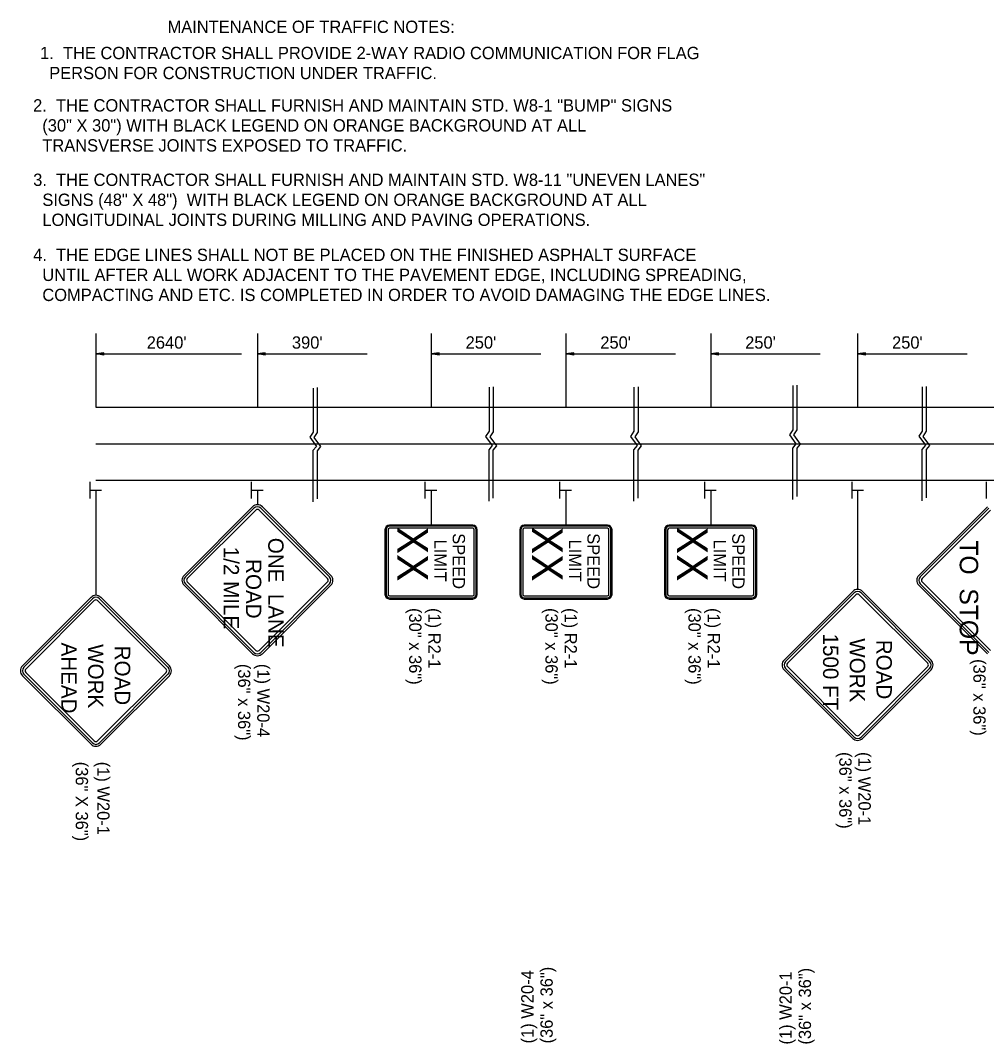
# Model space of a CAD drawing. Extents: x 1927831 to 1930787, y 596452 to 597699.
# Drawn here: x 1927871.5 to 1928342.4, y 597195.5 to 597694.1 of the extents above; entities that cross this region are included whole.
import ezdxf

# ---------------------------------------------------------------- set-up
doc = ezdxf.new("R2010")
doc.units = 0
for name, color, linetype in [('Default', 7, 'Continuous'), ('P_TC_Signs_Permanent', 7, 'Continuous'), ('P_TC_Signs_Temporary', 7, 'Continuous'), ('R_Border', 7, 'Continuous')]:
    doc.layers.add(name, color=color, linetype=linetype)

msp = doc.modelspace()

# ---------------------------------------------------------------- linework, layer by layer
at = {"layer": 'Default'}
for p, q in [((1927908.3, 597541.61), (1927908.3, 597505.58)), ((1927987.03, 597541.61), (1927987.03, 597505.56)), ((1928071.69, 597541.61), (1928071.69, 597505.58)), ((1928137.35, 597541.61), (1928137.35, 597505.58)), ((1928207.95, 597541.61), (1928207.95, 597505.58)), ((1928279.55, 597541.61), (1928279.55, 597505.58)), ((1927912.18, 597532.14), (1927908.34, 597531.57)), ((1927912.18, 597530.99), (1927908.34, 597531.57)), ((1927908.34, 597531.57), (1927979.22, 597531.57)), ((1927912.18, 597532.05), (1927908.98, 597531.57)), ((1927912.18, 597531.09), (1927908.98, 597531.57)), ((1927912.18, 597531.95), (1927909.64, 597531.57)), ((1927912.18, 597531.18), (1927909.64, 597531.57)), ((1927912.18, 597531.85), (1927910.28, 597531.57)), ((1927912.18, 597531.28), (1927910.28, 597531.57)), ((1927912.18, 597531.75), (1927910.93, 597531.57)), ((1927912.18, 597531.38), (1927910.93, 597531.57)), ((1927912.18, 597531.66), (1927911.57, 597531.57)), ((1927912.18, 597531.48), (1927911.57, 597531.57)), ((1927912.18, 597530.99), (1927912.18, 597532.14)), ((1927990.87, 597532.14), (1927987.03, 597531.57)), ((1927990.87, 597530.99), (1927987.03, 597531.57)), ((1927987.03, 597531.57), (1928040.44, 597531.57)), ((1927990.87, 597532.05), (1927987.67, 597531.57)), ((1927990.87, 597531.09), (1927987.67, 597531.57)), ((1927990.87, 597531.95), (1927988.33, 597531.57)), ((1927990.87, 597531.18), (1927988.33, 597531.57)), ((1927990.87, 597531.85), (1927988.97, 597531.57)), ((1927990.87, 597531.28), (1927988.97, 597531.57)), ((1927990.87, 597531.75), (1927989.62, 597531.57)), ((1927990.87, 597531.38), (1927989.62, 597531.57)), ((1927990.87, 597531.66), (1927990.26, 597531.57)), ((1927990.87, 597531.48), (1927990.26, 597531.57)), ((1927990.87, 597530.99), (1927990.87, 597532.14)), ((1928075.53, 597532.14), (1928071.69, 597531.57)), ((1928071.69, 597531.57), (1928125.09, 597531.57)), ((1928075.53, 597530.99), (1928071.69, 597531.57)), ((1928075.53, 597532.05), (1928072.33, 597531.57)), ((1928075.53, 597531.09), (1928072.33, 597531.57)), ((1928075.53, 597531.95), (1928072.99, 597531.57)), ((1928075.53, 597531.18), (1928072.99, 597531.57)), ((1928075.53, 597531.85), (1928073.63, 597531.57)), ((1928075.53, 597531.28), (1928073.63, 597531.57)), ((1928075.53, 597531.75), (1928074.28, 597531.57)), ((1928075.53, 597531.38), (1928074.28, 597531.57)), ((1928075.53, 597531.66), (1928074.92, 597531.57)), ((1928075.53, 597531.48), (1928074.92, 597531.57)), ((1928075.53, 597530.99), (1928075.53, 597532.14)), ((1928141.18, 597532.14), (1928137.35, 597531.57)), ((1928137.35, 597531.57), (1928190.75, 597531.57)), ((1928141.18, 597530.99), (1928137.35, 597531.57)), ((1928141.18, 597532.05), (1928137.99, 597531.57)), ((1928141.18, 597531.09), (1928137.99, 597531.57)), ((1928141.18, 597531.95), (1928138.65, 597531.57)), ((1928141.18, 597531.18), (1928138.65, 597531.57)), ((1928141.18, 597531.85), (1928139.29, 597531.57)), ((1928141.18, 597531.28), (1928139.29, 597531.57)), ((1928141.18, 597531.75), (1928139.94, 597531.57)), ((1928141.18, 597531.38), (1928139.94, 597531.57)), ((1928141.18, 597531.66), (1928140.58, 597531.57)), ((1928141.18, 597531.48), (1928140.58, 597531.57)), ((1928141.18, 597530.99), (1928141.18, 597532.14)), ((1928211.79, 597532.14), (1928207.95, 597531.57)), ((1928207.95, 597531.57), (1928261.36, 597531.59)), ((1928211.79, 597530.99), (1928207.95, 597531.57)), ((1928211.79, 597532.05), (1928208.6, 597531.57)), ((1928211.79, 597531.09), (1928208.6, 597531.57)), ((1928211.79, 597531.95), (1928209.26, 597531.57)), ((1928211.79, 597531.18), (1928209.26, 597531.57)), ((1928211.79, 597531.85), (1928209.89, 597531.57)), ((1928211.79, 597531.28), (1928209.89, 597531.57)), ((1928211.79, 597531.75), (1928210.55, 597531.57)), ((1928211.79, 597531.38), (1928210.55, 597531.57)), ((1928211.79, 597531.66), (1928211.19, 597531.57)), ((1928211.79, 597531.48), (1928211.19, 597531.57)), ((1928211.79, 597530.99), (1928211.79, 597532.14)), ((1928283.39, 597532.16), (1928279.55, 597531.59)), ((1928279.55, 597531.59), (1928332.95, 597531.59)), ((1928283.39, 597531.01), (1928279.55, 597531.59)), ((1928283.39, 597532.07), (1928280.19, 597531.59)), ((1928283.39, 597531.11), (1928280.19, 597531.59)), ((1928283.39, 597531.97), (1928280.85, 597531.59)), ((1928283.39, 597531.2), (1928280.85, 597531.59)), ((1928283.39, 597531.87), (1928281.49, 597531.59)), ((1928283.39, 597531.3), (1928281.49, 597531.59)), ((1928283.39, 597531.77), (1928282.14, 597531.59)), ((1928283.39, 597531.4), (1928282.14, 597531.59)), ((1928283.39, 597531.68), (1928282.78, 597531.59)), ((1928283.39, 597531.5), (1928282.78, 597531.59)), ((1928283.39, 597531.01), (1928283.39, 597532.16)), ((1927908.3, 597505.58), (1928044.85, 597505.58)), ((1928044.85, 597505.58), (1929173.7, 597505.58)), ((1927908.3, 597487.79), (1929173.7, 597487.79)), ((1927905.45, 597461.2), (1927905.45, 597469.2)), ((1927908.3, 597470), (1928044.85, 597470)), ((1927984.18, 597461.2), (1927984.18, 597469.2)), ((1928044.85, 597470), (1929173.7, 597470)), ((1928068.84, 597461.2), (1928068.84, 597469.2)), ((1928134.5, 597461.2), (1928134.5, 597469.2)), ((1928205.1, 597461.2), (1928205.1, 597469.2)), ((1928276.87, 597461.2), (1928276.87, 597469.2)), ((1928342.35, 597461.2), (1928342.35, 597469.2)), ((1927905.57, 597465.18), (1927911.03, 597465.18)), ((1927984.3, 597465.18), (1927989.77, 597465.18)), ((1928068.96, 597465.18), (1928074.42, 597465.18)), ((1928134.61, 597465.18), (1928140.08, 597465.18)), ((1928205.22, 597465.18), (1928210.69, 597465.18)), ((1928276.99, 597465.18), (1928282.45, 597465.18))]:
    msp.add_line(p, q, dxfattribs=at)
for points in [[(1928014.17, 597514.95), (1928014.17, 597493.43), (1928012.5, 597490.96), (1928015.74, 597486.53), (1928014.04, 597484.48), (1928014.03, 597459.46)], [(1928016.21, 597515.15), (1928016.21, 597493.34), (1928014.55, 597490.87), (1928017.79, 597486.44), (1928016.08, 597484.4), (1928016.08, 597460.9)], [(1928099.91, 597515.4), (1928099.91, 597493.87), (1928098.25, 597491.4), (1928101.48, 597486.97), (1928099.78, 597484.93), (1928099.77, 597459.9)], [(1928101.95, 597515.49), (1928101.95, 597493.69), (1928100.29, 597491.21), (1928103.53, 597486.78), (1928101.82, 597484.74), (1928101.82, 597461.24)], [(1928170.52, 597515.4), (1928170.52, 597493.87), (1928168.85, 597491.4), (1928172.09, 597486.97), (1928170.39, 597484.93), (1928170.38, 597459.9)], [(1928172.56, 597515.49), (1928172.56, 597493.69), (1928170.9, 597491.21), (1928174.14, 597486.78), (1928172.43, 597484.74), (1928172.43, 597461.24)], [(1928247.96, 597516.18), (1928247.96, 597494.66), (1928246.3, 597492.19), (1928249.53, 597487.76), (1928247.83, 597485.71), (1928247.82, 597460.68)], [(1928250, 597516.37), (1928250, 597494.57), (1928248.34, 597492.1), (1928251.58, 597487.67), (1928249.87, 597485.62), (1928249.87, 597462.12)], [(1928311, 597515.51), (1928311, 597493.99), (1928309.34, 597491.51), (1928312.58, 597487.08), (1928310.87, 597485.04), (1928310.87, 597460.01)], [(1928313.04, 597515.7), (1928313.04, 597493.9), (1928311.38, 597491.43), (1928314.62, 597487), (1928312.91, 597484.95), (1928312.91, 597461.45)]]:
    msp.add_lwpolyline(points, dxfattribs=at)
at = {"layer": 'P_TC_Signs_Permanent'}
for p, q in [((1928342.81, 597457.08), (1928309.4, 597423.67)), ((1928343.48, 597456.42), (1928310.07, 597423.01)), ((1928344.41, 597455.49), (1928310.99, 597422.08)), ((1928049.19, 597445.9), (1928049.19, 597414.4)), ((1928049.75, 597445.9), (1928049.75, 597414.4)), ((1928050.69, 597445.9), (1928050.69, 597414.4)), ((1928091.94, 597448.15), (1928051.44, 597448.15)), ((1928091.94, 597447.59), (1928051.44, 597447.59)), ((1928091.94, 597446.65), (1928051.44, 597446.65)), ((1928092.69, 597414.4), (1928092.69, 597445.9)), ((1928093.63, 597414.4), (1928093.63, 597445.9)), ((1928094.19, 597414.4), (1928094.19, 597445.9)), ((1928114.85, 597445.9), (1928114.85, 597414.4)), ((1928115.41, 597445.9), (1928115.41, 597414.4)), ((1928116.35, 597445.9), (1928116.35, 597414.4)), ((1928157.6, 597448.15), (1928117.1, 597448.15)), ((1928157.6, 597447.59), (1928117.1, 597447.59)), ((1928157.6, 597446.65), (1928117.1, 597446.65)), ((1928158.35, 597414.4), (1928158.35, 597445.9)), ((1928159.28, 597414.4), (1928159.28, 597445.9)), ((1928159.85, 597414.4), (1928159.85, 597445.9)), ((1928185.45, 597445.9), (1928185.45, 597414.4)), ((1928186.02, 597445.9), (1928186.02, 597414.4)), ((1928186.95, 597445.9), (1928186.95, 597414.4)), ((1928228.2, 597448.15), (1928187.7, 597448.15)), ((1928228.2, 597447.59), (1928187.7, 597447.59)), ((1928228.2, 597446.65), (1928187.7, 597446.65)), ((1928228.95, 597414.4), (1928228.95, 597445.9)), ((1928229.89, 597414.4), (1928229.89, 597445.9)), ((1928230.45, 597414.4), (1928230.45, 597445.9)), ((1928310.07, 597419.56), (1928343.48, 597386.15)), ((1928310.99, 597420.49), (1928344.41, 597387.08)), ((1928309.4, 597418.89), (1928342.81, 597385.48)), ((1928051.44, 597413.65), (1928091.94, 597413.65)), ((1928051.44, 597412.71), (1928091.94, 597412.71)), ((1928051.44, 597412.15), (1928091.94, 597412.15)), ((1928117.1, 597413.65), (1928157.6, 597413.65)), ((1928117.1, 597412.71), (1928157.6, 597412.71)), ((1928117.1, 597412.15), (1928157.6, 597412.15)), ((1928187.7, 597413.65), (1928228.2, 597413.65)), ((1928187.7, 597412.71), (1928228.2, 597412.71)), ((1928187.7, 597412.15), (1928228.2, 597412.15))]:
    msp.add_line(p, q, dxfattribs=at)
for centre, radius, start, end in [((1928051.44, 597445.9), 2.25, 90, 180), ((1928051.44, 597445.9), 1.69, 90, 180), ((1928051.44, 597445.9), 0.75, 90, 180), ((1928091.94, 597445.9), 2.25, 360, 90), ((1928091.94, 597445.9), 1.69, 360, 90), ((1928091.94, 597445.9), 0.75, 360, 90), ((1928117.1, 597445.9), 2.25, 90, 180), ((1928117.1, 597445.9), 1.69, 90, 180), ((1928117.1, 597445.9), 0.75, 90, 180), ((1928157.6, 597445.9), 2.25, 360, 90), ((1928157.6, 597445.9), 1.69, 360, 90), ((1928157.6, 597445.9), 0.75, 360, 90), ((1928187.7, 597445.9), 2.25, 90, 180), ((1928187.7, 597445.9), 1.69, 90, 180), ((1928187.7, 597445.9), 0.75, 90, 180), ((1928228.2, 597445.9), 2.25, 360, 90), ((1928228.2, 597445.9), 1.69, 360, 90), ((1928228.2, 597445.9), 0.75, 360, 90), ((1928311.79, 597421.28), 3.37, 135, 225), ((1928311.79, 597421.28), 2.44, 135, 225), ((1928311.79, 597421.28), 1.13, 135, 225), ((1928051.44, 597414.4), 2.25, 180, 270), ((1928051.44, 597414.4), 1.69, 180, 270), ((1928051.44, 597414.4), 0.75, 180, 270), ((1928091.94, 597414.4), 2.25, 270, 360), ((1928091.94, 597414.4), 1.69, 270, 360), ((1928091.94, 597414.4), 0.75, 270, 360), ((1928117.1, 597414.4), 2.25, 180, 270), ((1928117.1, 597414.4), 1.69, 180, 270), ((1928117.1, 597414.4), 0.75, 180, 270), ((1928157.6, 597414.4), 2.25, 270, 360), ((1928157.6, 597414.4), 1.69, 270, 360), ((1928157.6, 597414.4), 0.75, 270, 360), ((1928187.7, 597414.4), 2.25, 180, 270), ((1928187.7, 597414.4), 1.69, 180, 270), ((1928187.7, 597414.4), 0.75, 180, 270), ((1928228.2, 597414.4), 2.25, 270, 360), ((1928228.2, 597414.4), 1.69, 270, 360), ((1928228.2, 597414.4), 0.75, 270, 360)]:
    msp.add_arc(centre, radius, start, end, dxfattribs=at)
at = {"layer": 'P_TC_Signs_Temporary'}
for p, q in [((1927951.24, 597423.67), (1927984.65, 597457.08)), ((1927951.9, 597423), (1927985.31, 597456.42)), ((1927952.83, 597422.08), (1927986.24, 597455.49)), ((1927987.83, 597455.49), (1928021.24, 597422.08)), ((1927988.76, 597456.42), (1928022.17, 597423)), ((1927989.42, 597457.08), (1928022.83, 597423.67)), ((1927985.31, 597386.15), (1927951.9, 597419.56)), ((1927986.24, 597387.07), (1927952.83, 597420.49)), ((1928021.24, 597420.49), (1927987.83, 597387.07)), ((1928022.17, 597419.56), (1927988.76, 597386.15)), ((1927984.65, 597385.48), (1927951.24, 597418.89)), ((1928022.83, 597418.89), (1927989.42, 597385.48)), ((1928243.75, 597382.42), (1928277.16, 597415.83)), ((1928244.41, 597381.76), (1928277.82, 597415.17)), ((1928281.27, 597415.17), (1928314.68, 597381.76)), ((1928281.93, 597415.83), (1928315.35, 597382.42)), ((1927872.5, 597379.57), (1927905.91, 597412.98)), ((1927873.17, 597378.91), (1927906.58, 597412.32)), ((1927874.09, 597377.98), (1927907.5, 597411.39)), ((1927909.1, 597411.39), (1927942.51, 597377.98)), ((1927910.02, 597412.32), (1927943.43, 597378.91)), ((1927910.69, 597412.98), (1927944.1, 597379.57)), ((1928245.34, 597380.83), (1928278.75, 597414.24)), ((1928280.34, 597414.24), (1928313.75, 597380.83)), ((1927905.91, 597341.39), (1927872.5, 597374.8)), ((1927906.58, 597342.05), (1927873.17, 597375.46)), ((1927907.5, 597342.98), (1927874.09, 597376.39)), ((1927942.51, 597376.39), (1927909.1, 597342.98)), ((1927943.43, 597375.46), (1927910.02, 597342.05)), ((1927944.1, 597374.8), (1927910.69, 597341.39)), ((1928277.16, 597344.24), (1928243.75, 597377.65)), ((1928277.82, 597344.9), (1928244.41, 597378.31)), ((1928278.75, 597345.83), (1928245.34, 597379.24)), ((1928313.75, 597379.24), (1928280.34, 597345.83)), ((1928314.68, 597378.31), (1928281.27, 597344.9)), ((1928315.35, 597377.65), (1928281.93, 597344.24))]:
    msp.add_line(p, q, dxfattribs=at)
for centre, radius, start, end in [((1927987.03, 597454.69), 3.37, 45, 135), ((1927987.03, 597454.69), 2.44, 45, 135), ((1927987.03, 597454.69), 1.12, 45, 135), ((1927953.62, 597421.28), 3.37, 135, 225), ((1927953.62, 597421.28), 2.44, 135, 225), ((1927953.62, 597421.28), 1.13, 135, 225), ((1928020.44, 597421.28), 1.13, 315, 45), ((1928020.44, 597421.28), 2.44, 315, 45), ((1928020.44, 597421.28), 3.37, 315, 45), ((1928279.55, 597413.45), 3.37, 45, 135), ((1928279.55, 597413.45), 2.44, 45, 135), ((1928279.55, 597413.45), 1.12, 45, 135), ((1927908.3, 597410.59), 3.37, 45, 135), ((1927908.3, 597410.59), 2.44, 45, 135), ((1927908.3, 597410.59), 1.12, 45, 135), ((1927987.03, 597387.87), 3.37, 225, 315), ((1927987.03, 597387.87), 2.44, 225, 315), ((1927987.03, 597387.87), 1.12, 225, 315), ((1927874.89, 597377.18), 3.37, 135, 225), ((1927941.71, 597377.18), 3.37, 315, 45), ((1928246.14, 597380.04), 3.37, 135, 225), ((1928246.14, 597380.04), 2.44, 135, 225), ((1928246.14, 597380.04), 1.13, 135, 225), ((1928312.96, 597380.04), 1.13, 315, 45), ((1928312.96, 597380.04), 2.44, 315, 45), ((1928312.96, 597380.04), 3.37, 315, 45), ((1927874.89, 597377.18), 2.44, 135, 225), ((1927874.89, 597377.18), 1.13, 135, 225), ((1927941.71, 597377.18), 1.13, 315, 45), ((1927941.71, 597377.18), 2.44, 315, 45), ((1928279.55, 597346.63), 2.44, 225, 315), ((1928279.55, 597346.63), 1.12, 225, 315), ((1927908.3, 597343.77), 3.38, 225, 315), ((1927908.3, 597343.77), 2.44, 225, 315), ((1927908.3, 597343.77), 1.12, 225, 315), ((1928279.55, 597346.63), 3.37, 225, 315)]:
    msp.add_arc(centre, radius, start, end, dxfattribs=at)
at = {"layer": 'R_Border'}
for p, q in [((1927908.3, 597465.18), (1927908.3, 597413.97)), ((1927987.03, 597465.18), (1927987.03, 597458.07)), ((1928071.69, 597465.18), (1928071.69, 597448.15)), ((1928137.35, 597465.18), (1928137.35, 597448.15)), ((1928207.95, 597465.18), (1928207.95, 597448.15)), ((1928279.55, 597465.18), (1928279.55, 597416.82))]:
    msp.add_line(p, q, dxfattribs=at)

# ---------------------------------------------------------------- texts
at = {"layer": 'Default'}
for s, p in [("2640'", (1927933.06, 597534.16)), ("390'", (1928003.83, 597534.16)), ("250'", (1928088.49, 597534.18)), ("250'", (1928154.15, 597534.16)), ("250'", (1928224.76, 597534.16)), ("250'", (1928296.35, 597534.16))]:
    msp.add_text(s, height=6, rotation=360, dxfattribs=at).set_placement(p)
at = {"layer": 'P_TC_Signs_Permanent'}
for s, height, p in [('XX', 15, (1928055.19, 597447.45)), ('XX', 15, (1928120.85, 597447.45)), ('XX', 15, (1928191.45, 597447.45)), ('LIMIT', 6, (1928073.19, 597441.13)), ('SPEED', 6, (1928082.19, 597444.22)), ('LIMIT', 6, (1928138.85, 597441.13)), ('SPEED', 6, (1928147.85, 597444.22)), ('LIMIT', 6, (1928209.45, 597441.13)), ('SPEED', 6, (1928218.45, 597444.22))]:
    msp.add_text(s, height=height, rotation=270, dxfattribs=at).set_placement(p)
at = {"layer": 'P_TC_Signs_Temporary'}
for s, height, p in [('ONE  LANE', 7.5, (1927992.28, 597441.98)), ('TO  STOP', 9, (1928329.33, 597440.75)), ('1/2 MILE', 7.5, (1927970.53, 597437.6)), ('ROAD', 7.5, (1927981.41, 597431.59)), ('1500 FT', 7.5, (1928262.71, 597395.33)), (' AHEAD ', 7.5, (1927891.47, 597393.72)), ('WORK', 7.5, (1927904.49, 597390.17)), ('WORK', 7.5, (1928275.74, 597393.03)), (' ROAD ', 7.5, (1928288.76, 597395.06)), (' ROAD ', 7.5, (1927917.51, 597392.2))]:
    msp.add_text(s, height=height, rotation=270, dxfattribs=at).set_placement(p)
at = {"layer": 'R_Border'}
for s, height, rotation, p in [('MAINTENANCE OF TRAFFIC NOTES:', 6, 360, (1927943.21, 597688)), ('1.  THE CONTRACTOR SHALL PROVIDE 2-WAY RADIO COMMUNICATION FOR FLAG ', 6, 360, (1927881.08, 597675.24)), ('  PERSON FOR CONSTRUCTION UNDER TRAFFIC.', 6, 360, (1927881.08, 597665.49)), ('2.  THE CONTRACTOR SHALL FURNISH AND MAINTAIN STD. W8-1 "BUMP" SIGNS', 6, 360, (1927877.7, 597649.72)), ('  (30" X 30") WITH BLACK LEGEND ON ORANGE BACKGROUND AT ALL ', 6, 360, (1927877.7, 597639.97)), ('  TRANSVERSE JOINTS EXPOSED TO TRAFFIC.', 6, 360, (1927877.7, 597630.22)), ('3.  THE CONTRACTOR SHALL FURNISH AND MAINTAIN STD. W8-11 "UNEVEN LANES" ', 6, 360, (1927877.73, 597613.46)), ('  SIGNS (48" X 48")  WITH BLACK LEGEND ON ORANGE BACKGROUND AT ALL ', 6, 360, (1927877.73, 597603.71)), ('  LONGITUDINAL JOINTS DURING MILLING AND PAVING OPERATIONS.', 6, 360, (1927877.73, 597593.96)), ('4.  THE EDGE LINES SHALL NOT BE PLACED ON THE FINISHED ASPHALT SURFACE', 6, 360, (1927877.73, 597576.87)), ('  UNTIL AFTER ALL WORK ADJACENT TO THE PAVEMENT EDGE, INCLUDING SPREADING,', 6, 360, (1927877.73, 597567.12)), ('  COMPACTING AND ETC. IS COMPLETED IN ORDER TO AVOID DAMAGING THE EDGE LINES.', 6, 360, (1927877.73, 597557.37)), ('(30" x 36")', 5.9996, 270, (1928060.98, 597407.77)), ('(1) R2-1', 6, 270, (1928070.34, 597407.77)), ('(30" x 36")', 5.9996, 270, (1928127.39, 597407.77)), ('(1) R2-1', 6, 270, (1928136.75, 597407.77)), ('(30" x 36")', 5.9996, 270, (1928197.1, 597407.77)), ('(1) R2-1', 6, 270, (1928206.47, 597407.77)), ('(36" x 36")', 5.9996, 270, (1927977.56, 597380.55)), ('(1) W20-4', 6, 270, (1927986.92, 597380.55)), ('(36" x 36")', 5.9996, 270, (1928335.97, 597382.88)), ('(36" x 36")', 5.9996, 270, (1928270.63, 597337.6)), ('(1) W20-1', 6, 270, (1928279.99, 597337.6)), ('(36" X 36")', 6, 270, (1927898.46, 597332.87)), ('(1) W20-1', 6, 270, (1927908.94, 597332.87)), ('(1) W20-4', 6, 90, (1928121.59, 597195.58)), ('(36" x 36")', 5.9996, 90, (1928130.95, 597195.58)), ('(1) W20-1', 6, 90, (1928247.49, 597195.04)), ('(36" x 36")', 5.9996, 90, (1928256.85, 597195.04))]:
    msp.add_text(s, height=height, rotation=rotation, dxfattribs=at).set_placement(p)

doc.saveas('drawing.dxf')
